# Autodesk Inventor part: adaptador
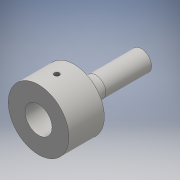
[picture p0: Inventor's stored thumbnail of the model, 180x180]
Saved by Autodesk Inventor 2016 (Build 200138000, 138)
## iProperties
Created: 2017-06
Part Number: adaptador
Material: Generic
Document SubType Name: Modeling
Designer: laboratorioesan
Density: 1 g/cm^3
Appearance: Default
Author: laboratorioesan
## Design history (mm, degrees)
sketch "Sketch1"
  geometry: C1 r 8 at (0, 0); C2 r 18 at (0, 0); 1 further point
  constraints: 2 centre point, 2 coincident
  dimensions: "d0" = 16 diameter of C1; "d1" = 36 diameter of C2
extrude "Extrusion1" new body sketch "Sketch1" distance "d2" = 21; taper "d3" = 0 deg
sketch "Sketch2"
  geometry: C1 r 8 at (0, 0) reference; C2 r 18 at (0, 0) reference; C3 r 12 at (0, 0); 1 further point
  constraints: 1 centre point, 1 coincident
  dimensions: "d4" = 24 diameter of C3
extrude "Extrusion2" join sketch "Sketch2" distance "d5" = 5; taper "d6" = 0 deg
sketch "Sketch3"
  geometry: C1 r 6 at (0, 0); 1 further point
  constraints: 1 centre point, 1 coincident
  dimensions: "d7" = 12 diameter of C1
extrude "Extrusion3" join sketch "Sketch3" distance "d8" = 35; taper "d9" = 0 deg
fillet "Fillet1" dims "d10" = 10
fillet "Fillet2" dims "d11" = 10
fillet "Fillet3" dims "d12" = 1
sketch "Sketch4"
  geometry: L1 (18, 21)-(-18, 21) reference; L2 (-18, 0)-(18, 0) reference; L3 (-8, 20)-(8, 20) reference; C1 r 1.5 at (0, 10.795); 1 further point
  constraints: 1 centre point
  dimensions: "d13" = 3 diameter of C1
extrude "Extrusion4" cut sketch "Sketch4" stored distance "d14" = 100; taper "d15" = 0 deg
body "Solid1"
node "Projected Loop1"
node "Projected Loop2"
